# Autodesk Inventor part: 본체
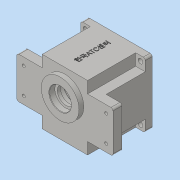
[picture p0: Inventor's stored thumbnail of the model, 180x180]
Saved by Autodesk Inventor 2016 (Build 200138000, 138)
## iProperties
Created: 2020-08
Part Number: 본체
Material: 일반
Document SubType Name: Modeling
Designer: User
Density: 1 g/cm^3
Appearance: 기본값
Author: User
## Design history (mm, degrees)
sketch "스케치1"
  geometry: L1 (-33, 47)-(33, 47); L2 (33, 47)-(33, -47); L3 (33, -47)-(-33, -47); L4 (-33, -47)-(-33, 47); L5 (-33, 47)-(33, -47); L6 (33, 47)-(-33, -47); L7 (-70, 30)-(70, 30); L8 (70, 30)-(70, -30); L9 (70, -30)-(-70, -30); L10 (-70, -30)-(-70, 30); L11 (-70, 30)-(70, -30); L12 (70, 30)-(-70, -30); 1 further point
  constraints: 24 end point, 4 midpoint, 4 parallel, 2 horizontal, 2 perpendicular
  dimensions: "d0" = 66 distance of L2.end L3.end; "d1" = 94 distance of L1.end L2.end; "d2" = 140 distance of L8.end L9.end; "d3" = 60 distance of L7.end L8.end
extrude "돌출1" new body sketch "스케치1" distance "d4" = 13; taper "d5" = 0 deg
sketch "스케치2"
  geometry: L1 (-47, 47)-(47, 47); L2 (47, 47)-(47, -47); L3 (47, -47)-(-47, -47); L4 (-47, -47)-(-47, 47); L5 (-47, 47)-(47, -47); L6 (47, 47)-(-47, -47); 1 further point
  constraints: 12 end point, 2 midpoint, 2 parallel, 1 horizontal, 1 perpendicular
  dimensions: "d6" = 94 distance of L2.end L3.end; "d7" = 94 distance of L1.end L2.end
extrude "돌출2" join sketch "스케치2" distance "d8" = 67; taper "d9" = 0 deg
sketch "스케치3"
  geometry: L1 (-47, 30)-(-33, 30) reference; L2 (-33, 30)-(-33, 47) reference; L3 (-33, 47)-(-47, 47) reference; L4 (-47, 47)-(-47, 30) reference; L5 (-33, -47)-(-33, -30) reference; L6 (-33, -30)-(-47, -30) reference; L7 (-47, -30)-(-47, -47) reference; L8 (-47, -47)-(-33, -47) reference; L9 (33, -30)-(33, -47) reference; L10 (33, -47)-(47, -47) reference; L11 (47, -47)-(47, -30) reference; L12 (47, -30)-(33, -30) reference; L13 (33, 30)-(47, 30) reference; L14 (47, 30)-(47, 47) reference; L15 (47, 47)-(33, 47) reference; L16 (33, 47)-(33, 30) reference; 1 further point
extrude "돌출3" cut sketch "스케치3" distance "d10" = 57; taper "d11" = 0 deg
sketch "스케치4"
  geometry: C1 r 27.5 at (0, 11); 1 further point
  constraints: 1 centre point, 1 vertical alignment
  dimensions: "d12" = 55 diameter of C1; "d13" = 11 distance of point (0, 0) C1.centre
extrude "돌출4" join sketch "스케치4" distance "d14" = 7; taper "d15" = 0 deg
sketch "스케치5"
  geometry: C1 r 16 at (0, 0); C2 r 27.5 at (0, 0) reference; 1 further point
  constraints: 1 centre point, 1 concentric
  dimensions: "d16" = 32 diameter of C1
extrude "돌출5" cut sketch "스케치5" distance "d17" = 8.3; taper "d18" = 0 deg
sketch "스케치6"
  geometry: C1 r 12.5 at (0, 0); C2 r 16 at (0, 0) reference; 1 further point
  constraints: 1 centre point, 1 concentric
  dimensions: "d19" = 25 diameter of C1
extrude "돌출6" cut sketch "스케치6" distance "d20" = 4.7; taper "d21" = 0 deg
sketch "스케치7"
  geometry: C1 r 43 at (0, 0); 1 further point
  constraints: 1 centre point, 1 coincident
  dimensions: "d22" = 86 diameter of C1
extrude "돌출7" cut sketch "스케치7" distance "d23" = 9; taper "d24" = 0 deg
sketch "스케치8"
  geometry: C1 r 40 at (0, 0); C2 r 43 at (0, 0) reference; 1 further point
  constraints: 1 centre point, 1 concentric
  dimensions: "d25" = 80 diameter of C1
extrude "돌출8" cut sketch "스케치8" distance "d26" = 71; taper "d27" = 0 deg
sketch "스케치9"
  geometry: C1 r 27.5 at (0, 11) reference; C2 r 21 at (0, 11); C3 r 15 at (0, -20); 1 further point
  constraints: 2 centre point, 1 coincident, 1 vertical alignment
  dimensions: "d28" = 21 radius of C2; "d29" = 15 radius of C3; "d30" = 20 distance of point (0, 0) C3.centre
extrude "돌출9" join sketch "스케치9" distance "d31" = 7; taper "d32" = 0 deg
sketch "스케치10"
  geometry: C1 r 17.5 at (0, 11); A1 r 21 centre (0, 11) between (8.978, -7.984) and (-8.978, -7.984) reference; A2 r 21 centre (0, 11) between (8.978, -7.984) and (-8.978, -7.984) reference; A3 r 15 centre (0, -20) between (-8.978, -7.984) and (8.978, -7.984) reference; 1 further point
  constraints: 1 centre point, 1 coincident
  dimensions: "d33" = 35 diameter of C1
extrude "돌출10" cut sketch "스케치10" distance "d34" = 10; taper "d35" = 0 deg
sketch "스케치11"
  geometry: C1 r 11 at (0, -20); A1 r 15 centre (0, -20) between (-8.978, -7.984) and (8.978, -7.984) reference; 1 further point
  constraints: 1 centre point, 1 concentric
  dimensions: "d36" = 22 diameter of C1
extrude "돌출11" cut sketch "스케치11" distance "d37" = 7; taper "d38" = 0 deg
sketch "스케치12"
  geometry: C1 r 9.5 at (0, 0); C2 r 11 at (0, 0) reference; 1 further point
  constraints: 1 centre point, 1 concentric
  dimensions: "d39" = 19 diameter of C1
extrude "돌출12" cut sketch "스케치12" distance "d40" = 3; taper "d41" = 0 deg
sketch "스케치13" dims "d42" = 36
  geometry: A1 r 4 centre (36, 0) between (36.19, 3.995) and (36.19, -3.995); A2 r 3 centre (36.333, 6.992) between (36.19, 3.995) and (39.279, 7.559); A3 r 40 centre (0, 0) between (39.279, -7.559) and (39.279, 7.559) reference; A4 r 3 centre (36.333, -6.992) between (39.279, -7.559) and (36.19, -3.995); 2 further points
  constraints: 8 point on circle, 4 tangent, 3 centre point, 2 horizontal alignment, 1 coincident, 2 other
  dimensions: "d43" = 4 radius of A1; "d44" = 3 radius of A2; "d45" = 3 radius of A4
extrude "돌출13" join sketch "스케치13" distance "d46" = 62; taper "d47" = 0 deg
sketch "스케치14"
  geometry: A1 r 4 centre (36, 0) between (36.19, 3.995) and (36.19, -3.995) reference; 1 further point
hole "구멍1" sketch "스케치14" at (36, 0) diameter "d48" = 3.242; stored, may be unused: countersink angle "d52" = 90 deg, drill point angle "d54" = 118 deg; dims "d49" = 7, "d50" = 4, "d51" = 2, "d53" = 9
sketch "스케치15"
  geometry: 2 further points
  dimensions: "d55" = 60 horizontal distance of point (0, 0) point (-60, 19); "d56" = 19 vertical distance of point (0, 0) point (-60, 19)
hole "구멍2" sketch "스케치15" at (-60, 19) diameter "d57" = 4.5; stored, may be unused: countersink angle "d61" = 90 deg, drill point angle "d63" = 118 deg; dims "d58" = 7, "d59" = 10, "d60" = 5, "d62" = 13
sketch "스케치16"
  geometry: C1 r 3.5 at (-40, 40); 1 further point
  constraints: 1 centre point
  dimensions: "d70" = 7 diameter of C1; "d71" = 40 horizontal distance of point (0, 0) C1.centre; "d72" = 40 horizontal distance of point (0, 0) C1.centre
extrude "돌출14" cut sketch "스케치16" distance "d73" = 62; taper "d74" = 0 deg
fillet "모깎기1" dims "d81" = 3
chamfer "모따기1" distance "d82" = 1; stored, may be unused: second distance "d83" = 2, angle "d84" = 45 deg
chamfer "모따기2" distance "d85" = 0.8; stored, may be unused: second distance "d86" = 2, angle "d87" = 30 deg
chamfer "모따기3" distance "d88" = 1; stored, may be unused: second distance "d89" = 2, angle "d90" = 30 deg
fillet "모깎기2" dims "d91" = 3
fillet "모깎기3" dims "d92" = 3
sketch "스케치17"
  geometry: L1 (-11, 80)-(77, 80) reference; 2 further points
  constraints: 1 vertical alignment, 1 other
  dimensions: "d93" = 40 distance from line of L1 point (33, 40)
feature "엠보싱1" sketch "스케치17" dims "d0" = 66, "d1" = 94, "d94" = 0.5, "d95" = 0
node "솔리드1"
mirror "대칭1"
pattern_linear "직사각형 패턴1" dims "d66" = 120, "d69" = 38
pattern_linear "직사각형 패턴2" dims "d77" = 80
node "투영된 루프1"
node "투영된 루프2"
node "투영된 루프3"
node "투영된 루프4"
node "투영된 루프5"
